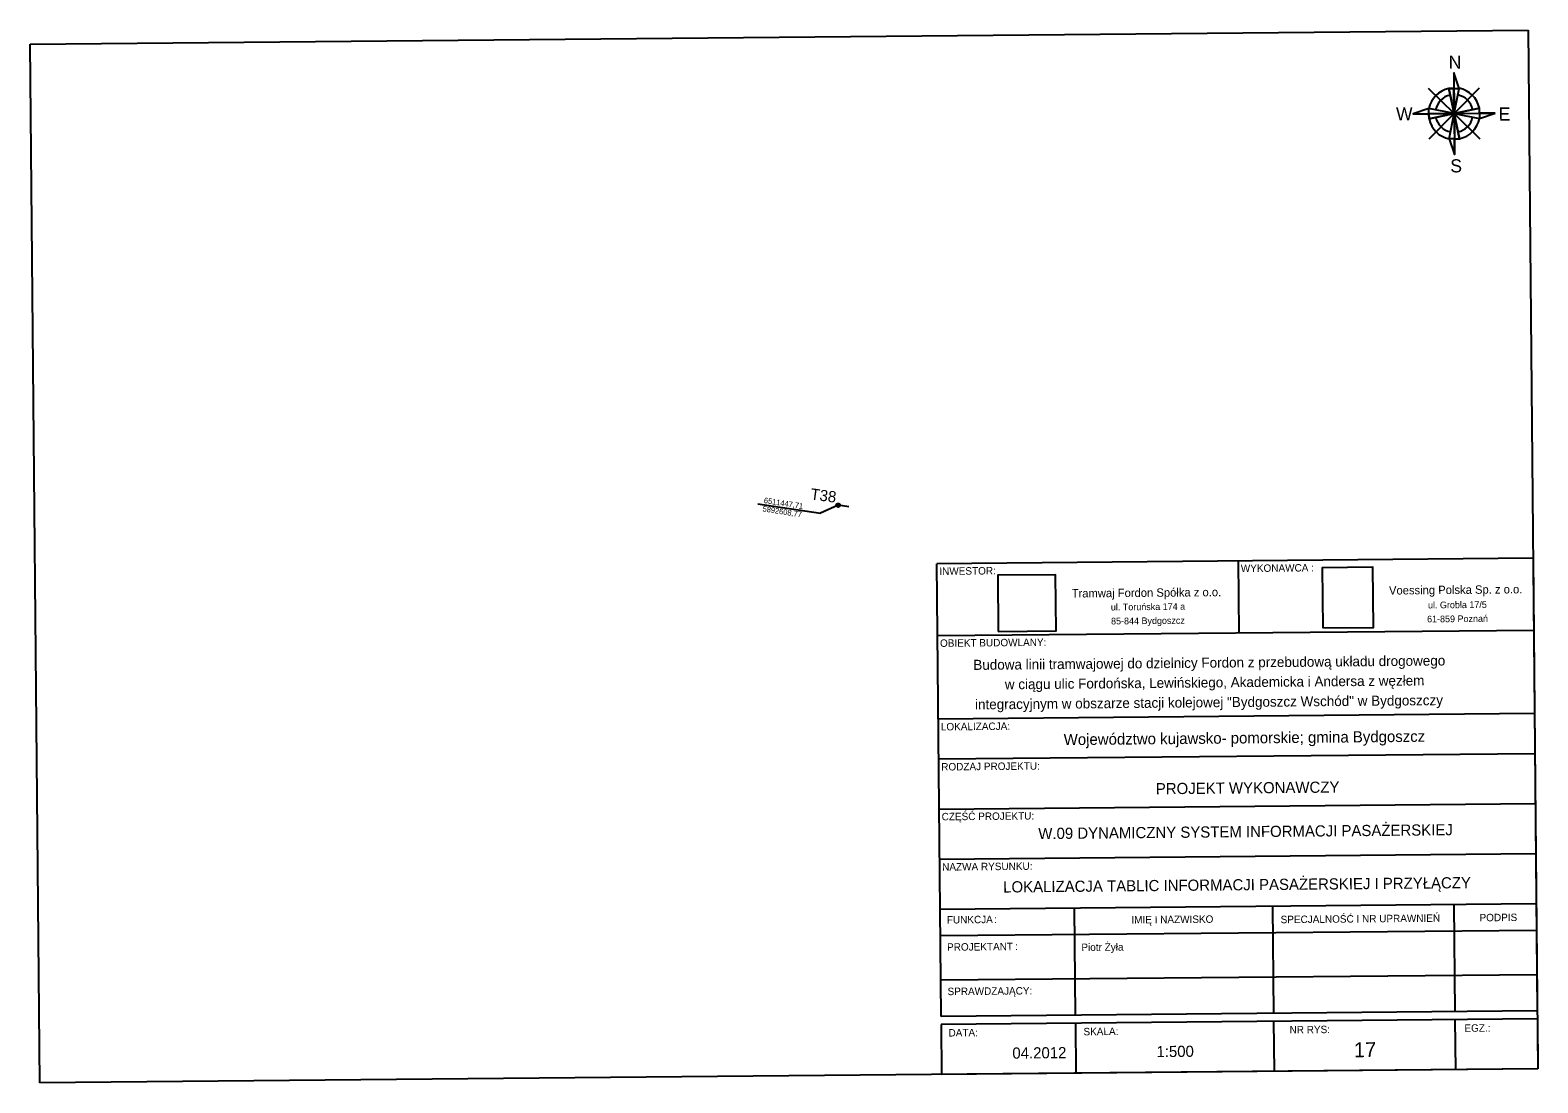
# Model space of a CAD drawing. Extents: x 6505045 to 6511721, y 5887996 to 5893535.
# Drawn here: x 6511339.3 to 6511541.6, y 5892531.2 to 5892672.5 of the extents above; entities that cross this region are included whole.
import ezdxf

# ---------------------------------------------------------------- set-up
doc = ezdxf.new("R2010")
doc.units = 0
for name, color, linetype in [('__legenda', 7, 'Continuous'), ('Default', 7, 'Continuous'), ('P_2 tablice LCD', 7, 'Continuous'), ('P_lokalizacja slupka', 7, 'Continuous'), ('P_opisy', 7, 'Continuous'), ('P_tabela', 7, 'Continuous'), ('P_wsporzedne', 7, 'Continuous'), ('P_znak północy', 7, 'Continuous'), ('SA_Linie-020', 7, 'Continuous'), ('SA_Stempel_Text-020', 7, 'Continuous'), ('SA_Stempel_Text-030', 7, 'Continuous'), ('SA_Stempel_Text-035', 7, 'Continuous'), ('SA_Unterschrift_Text', 7, 'Continuous')]:
    doc.layers.add(name, color=color, linetype=linetype)

msp = doc.modelspace()

# ---------------------------------------------------------------- linework, layer by layer
at = {"layer": '__legenda'}
msp.add_lwpolyline([(6511512.74, 5892592.3), (6511519.54, 5892592.37), (6511519.46, 5892600.43), (6511512.66, 5892600.37)], close=True, dxfattribs=at)
at = {"layer": 'Default'}
msp.add_lwpolyline([(6511469.21, 5892591.83), (6511476.95, 5892591.91), (6511476.88, 5892599.44), (6511469.14, 5892599.37)], close=True, dxfattribs=at)
at = {"layer": 'P_2 tablice LCD'}
msp.add_line((6511449.14, 5892608.56), (6511447.71, 5892608.77), dxfattribs=at)
at = {"layer": 'P_lokalizacja slupka'}
msp.add_circle((6511447.71, 5892608.77), 0.25, dxfattribs=at)
at = {"layer": 'P_tabela'}
for p, q in [((6511339.31, 5892670.67), (6511540.29, 5892672.55)), ((6511339.31, 5892670.67), (6511540.29, 5892672.55)), ((6511540.29, 5892672.55), (6511541.6, 5892533.1)), ((6511540.29, 5892672.55), (6511541.6, 5892533.1)), ((6511340.61, 5892531.22), (6511339.31, 5892670.67)), ((6511340.61, 5892531.22), (6511339.31, 5892670.67)), ((6511541.6, 5892533.1), (6511340.61, 5892531.22)), ((6511541.6, 5892533.1), (6511340.61, 5892531.22))]:
    msp.add_line(p, q, dxfattribs=at)
at = {"layer": 'P_wsporzedne'}
for p in [(6511436.93, 5892608.94), (6511447.71, 5892608.77)]:
    msp.add_line(p, (6511445.36, 5892607.68), dxfattribs=at)
at = {"layer": 'P_znak północy'}
for p, q in [((6511530.32, 5892666.87), (6511530.43, 5892655.83)), ((6511530.32, 5892666.87), (6511530.43, 5892655.83)), ((6511530.36, 5892661.35), (6511526.93, 5892664.73)), ((6511530.36, 5892661.35), (6511526.93, 5892664.73)), ((6511529.65, 5892664.72), (6511530.34, 5892664.73)), ((6511529.65, 5892664.72), (6511530.34, 5892664.73)), ((6511530.37, 5892661.35), (6511529.65, 5892664.72)), ((6511530.37, 5892661.35), (6511529.65, 5892664.72)), ((6511530.34, 5892664.73), (6511531.03, 5892664.73)), ((6511530.34, 5892664.73), (6511531.03, 5892664.73)), ((6511530.37, 5892661.36), (6511533.76, 5892664.79)), ((6511530.37, 5892661.36), (6511533.76, 5892664.79)), ((6511530.37, 5892661.35), (6511531.03, 5892664.73)), ((6511530.37, 5892661.35), (6511531.03, 5892664.73)), ((6511530.37, 5892661.35), (6511526.99, 5892662.01)), ((6511530.37, 5892661.35), (6511526.99, 5892662.01)), ((6511530.37, 5892661.35), (6511533.75, 5892662.07)), ((6511530.37, 5892661.35), (6511533.75, 5892662.07)), ((6511524.85, 5892661.29), (6511535.89, 5892661.4)), ((6511524.85, 5892661.29), (6511535.89, 5892661.4)), ((6511530.37, 5892661.36), (6511526.99, 5892657.9)), ((6511530.37, 5892661.36), (6511526.99, 5892657.9)), ((6511526.99, 5892661.31), (6511530.36, 5892661.35)), ((6511526.99, 5892661.31), (6511530.36, 5892661.35)), ((6511527, 5892660.62), (6511526.99, 5892661.31)), ((6511527, 5892660.62), (6511526.99, 5892661.31)), ((6511527, 5892660.62), (6511530.37, 5892661.35)), ((6511530.36, 5892661.35), (6511527, 5892660.62)), ((6511527, 5892660.62), (6511530.37, 5892661.35)), ((6511530.36, 5892661.35), (6511527, 5892660.62)), ((6511529.71, 5892657.96), (6511530.37, 5892661.35)), ((6511529.71, 5892657.96), (6511530.37, 5892661.35)), ((6511530.37, 5892661.36), (6511533.82, 5892657.96)), ((6511530.37, 5892661.36), (6511533.82, 5892657.96)), ((6511530.37, 5892661.35), (6511533.76, 5892660.69)), ((6511530.37, 5892661.35), (6511531.1, 5892657.97)), ((6511530.37, 5892661.35), (6511533.76, 5892660.69)), ((6511530.37, 5892661.35), (6511531.1, 5892657.97))]:
    msp.add_line(p, q, dxfattribs=at)
for points in [[(6511530.32, 5892666.87), (6511530.34, 5892664.73), (6511530.34, 5892664.73), (6511531.03, 5892664.73), (6511530.32, 5892666.87)], [(6511530.32, 5892666.87), (6511530.34, 5892664.73), (6511530.34, 5892664.73), (6511531.03, 5892664.73), (6511530.32, 5892666.87)], [(6511530.37, 5892661.36), (6511530.34, 5892664.73), (6511529.65, 5892664.72), (6511530.37, 5892661.35), (6511530.37, 5892661.36)], [(6511530.37, 5892661.36), (6511530.34, 5892664.73), (6511529.65, 5892664.72), (6511530.37, 5892661.35), (6511530.37, 5892661.36)], [(6511526.99, 5892661.31), (6511526.99, 5892662.01), (6511524.85, 5892661.29), (6511526.99, 5892661.31)], [(6511526.99, 5892661.31), (6511526.99, 5892662.01), (6511524.85, 5892661.29), (6511526.99, 5892661.31)], [(6511530.37, 5892661.35), (6511530.37, 5892661.35), (6511530.38, 5892661.35), (6511533.75, 5892661.38), (6511533.75, 5892662.07), (6511530.37, 5892661.35)], [(6511530.37, 5892661.35), (6511530.37, 5892661.35), (6511530.38, 5892661.35), (6511533.75, 5892661.38), (6511533.75, 5892662.07), (6511530.37, 5892661.35)], [(6511530.36, 5892661.35), (6511526.99, 5892661.31), (6511527, 5892660.62), (6511530.36, 5892661.35)], [(6511530.36, 5892661.35), (6511526.99, 5892661.31), (6511527, 5892660.62), (6511530.36, 5892661.35)], [(6511530.41, 5892657.97), (6511531.1, 5892657.97), (6511530.37, 5892661.34), (6511530.41, 5892657.97)], [(6511530.41, 5892657.97), (6511531.1, 5892657.97), (6511530.37, 5892661.34), (6511530.41, 5892657.97)], [(6511535.89, 5892661.4), (6511533.75, 5892661.38), (6511533.76, 5892660.69), (6511535.89, 5892661.4)], [(6511535.89, 5892661.4), (6511533.75, 5892661.38), (6511533.76, 5892660.69), (6511535.89, 5892661.4)], [(6511530.41, 5892657.97), (6511529.71, 5892657.96), (6511530.43, 5892655.83), (6511530.41, 5892657.97)], [(6511530.41, 5892657.97), (6511529.71, 5892657.96), (6511530.43, 5892655.83), (6511530.41, 5892657.97)]]:
    msp.add_lwpolyline(points, dxfattribs=at)
for centre, radius, start, end in [((6511530.37, 5892661.35), 3.45, 102.0474, 168.9738), ((6511530.37, 5892661.35), 3.45, 102.0474, 168.9738), ((6511530.37, 5892661.36), 2.53, 102.1671, 169.2958), ((6511530.37, 5892661.36), 2.53, 102.1671, 169.2958), ((6511530.37, 5892661.36), 2.53, 11.7816, 78.9353), ((6511530.37, 5892661.36), 2.53, 11.7816, 78.9353), ((6511530.38, 5892661.35), 3.45, 12.0554, 79.0163), ((6511530.38, 5892661.35), 3.45, 12.0554, 79.0163), ((6511530.37, 5892661.34), 3.45, 192.0538, 259.0158), ((6511530.37, 5892661.34), 3.45, 192.0538, 259.0158), ((6511530.37, 5892661.36), 2.53, 192.3917, 259.0318), ((6511530.37, 5892661.36), 2.53, 192.3917, 259.0318), ((6511530.37, 5892661.36), 2.53, 282.0081, 348.6723), ((6511530.37, 5892661.36), 2.53, 282.0081, 348.6723), ((6511530.38, 5892661.34), 3.45, 282.0538, 349.0163), ((6511530.38, 5892661.34), 3.45, 282.0538, 349.0163)]:
    msp.add_arc(centre, radius, start, end, dxfattribs=at)
at = {"layer": 'SA_Linie-020'}
for p, q in [((6511540.96, 5892601.67), (6511460.96, 5892600.92)), ((6511501.41, 5892601.3), (6511501.5, 5892591.64)), ((6511540.96, 5892601.67), (6511541.52, 5892540.88)), ((6511461.39, 5892554.5), (6511460.96, 5892600.92)), ((6511461.05, 5892591.26), (6511541.05, 5892592.01)), ((6511541.15, 5892580.79), (6511461.15, 5892580.04)), ((6511541.2, 5892575.41), (6511461.2, 5892574.66)), ((6511541.26, 5892568.69), (6511461.27, 5892567.94)), ((6511541.26, 5892568.69), (6511461.27, 5892567.94)), ((6511541.33, 5892561.97), (6511461.33, 5892561.22)), ((6511541.39, 5892555.25), (6511461.39, 5892554.5)), ((6511461.53, 5892540.13), (6511461.39, 5892554.5)), ((6511479.55, 5892540.3), (6511479.41, 5892554.67)), ((6511505.99, 5892554.93), (6511506.12, 5892540.55)), ((6511530.32, 5892555.15), (6511530.46, 5892540.77)), ((6511541.42, 5892551.69), (6511461.43, 5892550.94)), ((6511541.48, 5892545.73), (6511461.48, 5892544.99)), ((6511541.52, 5892540.88), (6511461.53, 5892540.13)), ((6511541.53, 5892539.82), (6511461.54, 5892539.07)), ((6511461.54, 5892539.07), (6511461.6, 5892532.35)), ((6511479.56, 5892539.24), (6511479.62, 5892532.52)), ((6511506.13, 5892539.49), (6511506.2, 5892532.77)), ((6511530.47, 5892539.71), (6511530.53, 5892532.99)), ((6511541.53, 5892539.82), (6511541.6, 5892533.1)), ((6511541.6, 5892533.1), (6511461.6, 5892532.35))]:
    msp.add_line(p, q, dxfattribs=at)

# ---------------------------------------------------------------- texts
at = {"layer": 'P_opisy'}
msp.add_text('T38', height=1.501, rotation=352.3314, dxfattribs=at).set_placement((6511443.94, 5892609.56))
at = {"layer": 'P_wsporzedne'}
for s, p in [('6511447,71', (6511437.71, 5892609.07)), ('5892608,77', (6511437.54, 5892607.95))]:
    msp.add_text(s, height=0.751, rotation=351.0937, dxfattribs=at).set_placement(p)
at = {"layer": 'P_znak północy'}
for s, p in [('N', (6511529.64, 5892667.35)), ('N', (6511529.64, 5892667.35)), ('W', (6511522.58, 5892660.42)), ('W', (6511522.58, 5892660.42)), ('E', (6511536.35, 5892660.4)), ('E', (6511536.35, 5892660.4)), ('S', (6511529.86, 5892653.44)), ('S', (6511529.86, 5892653.44))]:
    msp.add_text(s, height=1.76, rotation=0.535, dxfattribs=at).set_placement(p)
at = {"layer": 'SA_Stempel_Text-020'}
for s, p in [('INWESTOR:', (6511461.3, 5892599.41)), ('WYKONAWCA :', (6511501.75, 5892599.79)), ('OBIEKT BUDOWLANY:', (6511461.39, 5892589.75)), ('LOKALIZACJA:', (6511461.5, 5892578.53)), ('RODZAJ PROJEKTU:', (6511461.55, 5892573.15)), ('CZĘŚĆ PROJEKTU:', (6511461.61, 5892566.46)), ('NAZWA RYSUNKU:', (6511461.68, 5892559.71)), ('FUNKCJA', (6511462.31, 5892552.61)), (':', (6511468.64, 5892552.67)), ('IMIĘ I NAZWISKO', (6511487.07, 5892552.61)), ('SPECJALNOŚĆ I NR UPRAWNIEŃ', (6511507.09, 5892552.65)), ('PODPIS', (6511533.78, 5892552.9)), ('PROJEKTANT', (6511462.34, 5892548.95)), (':', (6511471.47, 5892549.04)), ('SPRAWDZAJĄCY:', (6511462.4, 5892542.99)), ('DATA:', (6511462.53, 5892537.44)), ('SKALA:', (6511480.64, 5892537.6)), ('NR RYS:', (6511508.29, 5892537.85)), ('EGZ.:', (6511531.75, 5892538.07))]:
    msp.add_text(s, height=1, rotation=0.535, dxfattribs=at).set_placement(p)
at = {"layer": 'SA_Stempel_Text-030'}
for s, height, p in [('1:500', 1.5, (6511490.43, 5892534.67)), ('17', 2, (6511516.93, 5892534.66)), ('04.2012', 1.5, (6511471.1, 5892534.47))]:
    msp.add_text(s, height=height, rotation=0.535, dxfattribs=at).set_placement(p)
at = {"layer": 'SA_Stempel_Text-035'}
for s, height, p in [('Budowa linii tramwajowej do dzielnicy Fordon z przebudową układu drogowego', 1.35, (6511465.86, 5892586.66)), ('w ciągu ulic Fordońska, Lewińskiego, Akademicka i Andersa z węzłem', 1.35, (6511470.09, 5892584.05)), ('integracyjnym w obszarze stacji kolejowej "Bydgoszcz Wschód" w Bydgoszczy', 1.35, (6511466.09, 5892581.35)), ('Województwo kujawsko- pomorskie; gmina Bydgoszcz', 1.5, (6511477.99, 5892576.56)), ('PROJEKT WYKONAWCZY', 1.5, (6511490.35, 5892569.96)), ('W.09 DYNAMICZNY SYSTEM INFORMACJI PASAŻERSKIEJ', 1.5, (6511474.58, 5892563.94)), ('LOKALIZACJA TABLIC INFORMACJI PASAŻERSKIEJ I PRZYŁĄCZY', 1.5, (6511469.87, 5892556.77))]:
    msp.add_text(s, height=height, rotation=0.535, dxfattribs=at).set_placement(p)
at = {"layer": 'SA_Unterschrift_Text'}
for s, height, p in [('Tramwaj Fordon Spółka z o.o.', 1.125, (6511479.05, 5892596.37)), ('Voessing Polska Sp. z o.o.', 1.125, (6511521.63, 5892596.77)), ('ul. Toruńska 174 a', 0.9, (6511484.31, 5892594.64)), ('ul. Grobla 17/5', 0.9, (6511526.86, 5892594.91)), ('85-844 Bydgoszcz', 0.9, (6511484.34, 5892592.76)), ('61-859 Poznań', 0.9, (6511526.74, 5892593.03)), ('Piotr Żyła', 1, (6511480.36, 5892548.92))]:
    msp.add_text(s, height=height, rotation=0.535, dxfattribs=at).set_placement(p)

doc.saveas('drawing.dxf')
